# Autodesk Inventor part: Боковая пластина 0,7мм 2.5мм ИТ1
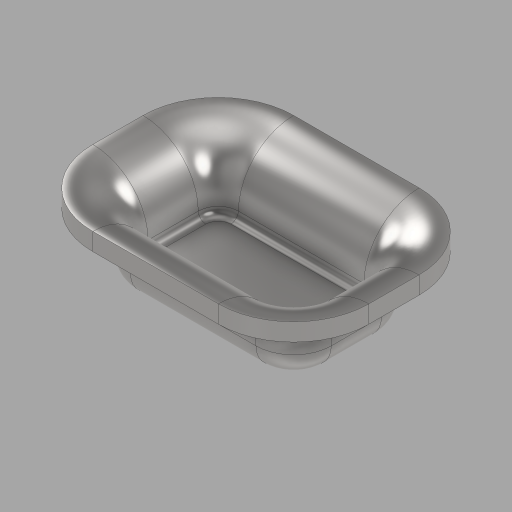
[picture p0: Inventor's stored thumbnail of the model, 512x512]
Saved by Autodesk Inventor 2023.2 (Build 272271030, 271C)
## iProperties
Created: 2025-02
Part Number: Боковая пластина 0,7мм 2.5мм ИТ1
Material: Типовые
Document SubType Name: Modeling
Designer: Артур
Density: 1 g/cm^3
Appearance: По умолчанию
Author: Артур
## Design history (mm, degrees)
sketch "Эскиз1"
  geometry: L1 (-2.5, 2.5)-(2.5, 2.5); L2 (4, 1)-(4, -1); L3 (2.5, -2.5)-(-2.5, -2.5); L4 (-4, -1)-(-4, 1); L5 (-4, 2.5)-(4, -2.5); L6 (4, 2.5)-(-4, -2.5); L7 (2.5, 4)-(-2.5, 4); L8 (-5.5, 1)-(-5.5, -1); L9 (-2.5, -4)-(2.5, -4); L10 (5.5, -1)-(5.5, 1); A1 r 1.5 centre (2.5, 1) between (4, 1) and (2.5, 2.5); A2 r 1.5 centre (2.5, -1) between (2.5, -2.5) and (4, -1); A3 r 1.5 centre (-2.5, -1) between (-4, -1) and (-2.5, -2.5); A4 r 1.5 centre (-2.5, 1) between (-2.5, 2.5) and (-4, 1); A5 r 3 centre (-2.5, 1) between (-2.5, 4) and (-5.5, 1); A6 r 3 centre (-2.5, -1) between (-5.5, -1) and (-2.5, -4); A7 r 3 centre (2.5, -1) between (2.5, -4) and (5.5, -1); A8 r 3 centre (2.5, 1) between (5.5, 1) and (2.5, 4); 2 further points
  constraints: 20 end point, 16 point on circle, 8 centre point, 8 point on line, 8 tangent, 4 parallel, 3 equal radius, 3 midpoint, 2 perpendicular, 1 horizontal, 7 other
  dimensions: "d0" = 8 distance of L5.end L6.end; "d1" = 5 distance of L6.start L5.end; "d2" = 1.5 radius of A1; "d3" = 1.5 radial gap between concentric circles of A1 A8; "d11" = 11 distance from line of point (-5.5, 0) L10 (derived)
extrude "Выдавливание1" new body sketch "Эскиз1" distance "d4" = 0.7; taper "d5" = 0 deg
extrude "Выдавливание2" join sketch "Эскиз1" distance "d6" = 2.5; taper "d7" = 0 deg
fillet "Сопряжение1" dims "d8" = 1.5
fillet "Сопряжение2" dims "d9" = 1
feature "Удаление грани1"
feature "Удаление грани2"
feature "Толщина1" dims "d10" = 0.7
node "Твердое тело1"
